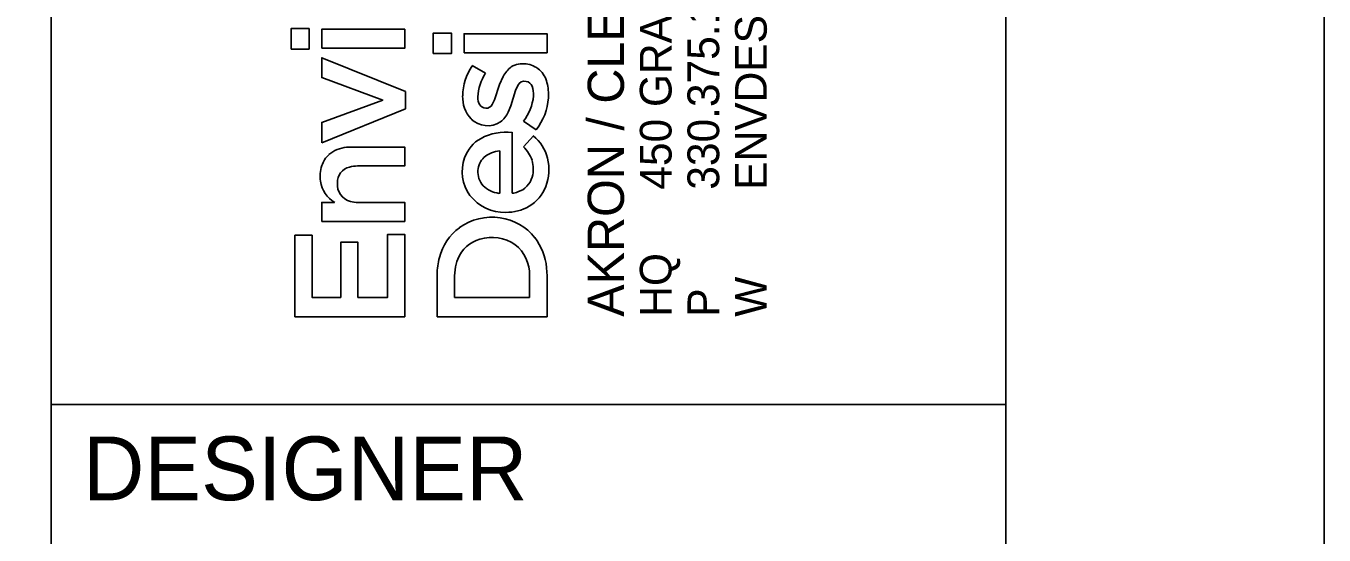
# Model space of a CAD drawing. Extents: x -0.2 to 34, y 0 to 22.
# Drawn here: x 31.961 to 34, y 2.295 to 3.094 of the extents above; entities that cross this region are included whole.
import ezdxf

# ---------------------------------------------------------------- set-up
doc = ezdxf.new("R2010")
doc.units = 0
for name, color, linetype in [('SH_Border', 7, 'Continuous'), ('SH_Cut_Line', 7, 'Continuous'), ('SH_Data', 7, 'Continuous')]:
    doc.layers.add(name, color=color, linetype=linetype)

msp = doc.modelspace()

# ---------------------------------------------------------------- linework, layer by layer
at = {"layer": 'SH_Border'}
for p, q in [((32, 0.5), (32, 21.5)), ((32, 2.5), (33.5, 2.5))]:
    msp.add_line(p, q, dxfattribs=at)
msp.add_lwpolyline([(1.5, 21.5), (33.5, 21.5), (33.5, 0.5), (1.5, 0.5)], close=True, dxfattribs=at)
at = {"layer": 'SH_Cut_Line'}
msp.add_lwpolyline([(0, 0), (34, 0), (34, 22), (0, 22)], close=True, dxfattribs=at)
at = {"layer": 'SH_Data'}
for p, q in [((32.3771, 3.0582), (32.3771, 3.0903)), ((32.3771, 3.0903), (32.4054, 3.0903)), ((32.4054, 3.0903), (32.4054, 3.0582)), ((32.4254, 3.0594), (32.4254, 3.0893)), ((32.4254, 3.0893), (32.5557, 3.0893)), ((32.5557, 3.0893), (32.5557, 3.0594)), ((32.6005, 3.0511), (32.6005, 3.0832)), ((32.6005, 3.0832), (32.6289, 3.0832)), ((32.6289, 3.0832), (32.6289, 3.0511)), ((32.6489, 3.0523), (32.6489, 3.0822)), ((32.6489, 3.0822), (32.7792, 3.0822)), ((32.7792, 3.0822), (32.7792, 3.0523)), ((32.5557, 3.0594), (32.4254, 3.0594)), ((32.4054, 3.0582), (32.3771, 3.0582)), ((32.4254, 3.0133), (32.4254, 3.0446)), ((32.4254, 3.0446), (32.5567, 2.9913)), ((32.6289, 3.0511), (32.6005, 3.0511)), ((32.7792, 3.0523), (32.6489, 3.0523)), ((32.6615, 3.0321), (32.6827, 3.0203)), ((32.5212, 2.978), (32.4254, 3.0133)), ((32.6967, 2.9787), (32.7048, 3.0026)), ((32.7048, 3.0026), (32.7104, 3.0153)), ((32.7334, 3.001), (32.7298, 2.9933)), ((32.4254, 2.9429), (32.5212, 2.978)), ((32.5567, 2.9913), (32.5567, 2.9644)), ((32.693, 2.9712), (32.6967, 2.9787)), ((32.7298, 2.9933), (32.7221, 2.9688)), ((32.5567, 2.9644), (32.4254, 2.9109)), ((32.7221, 2.9688), (32.7182, 2.9592)), ((32.4254, 2.9109), (32.4254, 2.9429)), ((32.7621, 2.9314), (32.742, 2.9447)), ((32.7245, 2.9275), (32.7246, 2.8319)), ((32.7423, 2.9046), (32.7577, 2.922)), ((32.4644, 2.904), (32.4729, 2.9044)), ((32.4729, 2.9044), (32.5557, 2.9044)), ((32.5557, 2.9044), (32.5557, 2.8746)), ((32.7049, 2.8318), (32.7049, 2.8983)), ((32.5557, 2.8746), (32.4814, 2.8746)), ((32.4254, 2.7875), (32.4254, 2.8173)), ((32.4254, 2.8173), (32.4455, 2.8173)), ((32.4822, 2.8173), (32.5557, 2.8173)), ((32.5557, 2.8173), (32.5557, 2.7876)), ((32.7036, 2.8317), (32.7049, 2.8318)), ((32.5557, 2.7876), (32.4254, 2.7875)), ((32.383, 2.6379), (32.383, 2.766)), ((32.383, 2.766), (32.4101, 2.766)), ((32.4101, 2.766), (32.4101, 2.6683)), ((32.455, 2.6683), (32.455, 2.7549)), ((32.455, 2.7549), (32.4822, 2.7549)), ((32.4822, 2.7549), (32.4822, 2.6683)), ((32.5286, 2.6683), (32.5286, 2.7672)), ((32.5286, 2.7672), (32.5557, 2.7672)), ((32.5557, 2.7672), (32.5557, 2.6379)), ((32.7785, 2.715), (32.7792, 2.7021)), ((32.6064, 2.638), (32.6064, 2.704)), ((32.6347, 2.7118), (32.6341, 2.7023)), ((32.6341, 2.7023), (32.6341, 2.6684)), ((32.7515, 2.6683), (32.7515, 2.7024)), ((32.7792, 2.7021), (32.7792, 2.638)), ((32.4101, 2.6683), (32.455, 2.6683)), ((32.4822, 2.6683), (32.5286, 2.6683)), ((32.6341, 2.6684), (32.7515, 2.6683)), ((32.5557, 2.6379), (32.383, 2.6379)), ((32.7792, 2.638), (32.6064, 2.638))]:
    msp.add_line(p, q, dxfattribs=at)
for points in [[(32.3771, 3.0582), (32.3771, 3.0903), (32.4054, 3.0903), (32.4054, 3.0582)], [(32.4254, 3.0594), (32.4254, 3.0893), (32.5557, 3.0893), (32.5557, 3.0594)], [(32.6005, 3.0511), (32.6005, 3.0832), (32.6289, 3.0832), (32.6289, 3.0511)], [(32.6489, 3.0523), (32.6489, 3.0822), (32.7792, 3.0822), (32.7792, 3.0523)], [(32.4254, 2.9109), (32.4254, 2.9429), (32.5212, 2.978), (32.4254, 3.0133), (32.4254, 3.0446), (32.5567, 2.9913), (32.5567, 2.9644)], [(32.383, 2.6379), (32.383, 2.766), (32.4101, 2.766), (32.4101, 2.6683), (32.455, 2.6683), (32.455, 2.7549), (32.4822, 2.7549), (32.4822, 2.6683), (32.5286, 2.6683), (32.5286, 2.7672), (32.5557, 2.7672), (32.5557, 2.6379)]]:
    msp.add_lwpolyline(points, close=True, dxfattribs=at)
for points in [[(32.6615, 3.0321), (32.6827, 3.0203)], [(32.693, 2.9712), (32.6967, 2.9787), (32.7048, 3.0026), (32.7104, 3.0153)], [(32.7334, 3.001), (32.7298, 2.9933), (32.7221, 2.9688), (32.7182, 2.9592)], [(32.7621, 2.9314), (32.742, 2.9447)], [(32.7245, 2.9275), (32.7246, 2.8319)], [(32.7423, 2.9046), (32.7577, 2.922)], [(32.4644, 2.904), (32.4729, 2.9044), (32.5557, 2.9044), (32.5557, 2.8746), (32.4814, 2.8746)], [(32.7036, 2.8317), (32.7049, 2.8318), (32.7049, 2.8983)], [(32.4254, 2.7875), (32.4254, 2.8173), (32.4455, 2.8173)], [(32.4822, 2.8173), (32.5557, 2.8173), (32.5557, 2.7876), (32.4254, 2.7875)], [(32.7785, 2.715), (32.7792, 2.7021), (32.7792, 2.638), (32.6064, 2.638)], [(32.6064, 2.638), (32.6064, 2.704)], [(32.6347, 2.7118), (32.6341, 2.7023), (32.6341, 2.6684), (32.7515, 2.6683), (32.7515, 2.7024)]]:
    msp.add_lwpolyline(points, dxfattribs=at)
for centre, radius, start, end in [((32.7364, 2.9826), 0.0897, 146.531, 178.7571), ((32.7364, 2.9826), 0.0897, 146.531, 178.7571), ((32.7452, 2.9789), 0.0749, 146.5112, 176.9101), ((32.7452, 2.9789), 0.0749, 146.5112, 176.9101), ((32.7466, 2.9971), 0.0405, 125.5118, 153.4159), ((32.7466, 2.9971), 0.0405, 125.5118, 153.4159), ((32.7406, 3.0026), 0.0326, 80.1719, 122.5197), ((32.7406, 3.0026), 0.0326, 80.1719, 122.5197), ((32.7428, 2.9982), 0.0367, 47.7934, 84.6892), ((32.7428, 2.9982), 0.0367, 47.7934, 84.6892), ((32.7379, 2.9946), 0.0427, 14.9966, 46.2063), ((32.7379, 2.9946), 0.0427, 14.9966, 46.2063), ((32.7438, 2.9963), 0.0114, 76.6609, 155.7053), ((32.7438, 2.9963), 0.0114, 76.6609, 155.7053), ((32.744, 2.9951), 0.0126, 21.5098, 78.5262), ((32.744, 2.9951), 0.0126, 21.5098, 78.5262), ((32.7259, 2.9877), 0.0321, 354.5726, 22.068), ((32.7259, 2.9877), 0.0321, 354.5726, 22.068), ((32.7104, 2.9867), 0.0712, 355.8306, 15.3914), ((32.7104, 2.9867), 0.0712, 355.8306, 15.3914), ((32.6967, 2.9824), 0.0501, 177.5366, 222.7932), ((32.6967, 2.9824), 0.0501, 177.5366, 222.7932), ((32.6931, 2.9823), 0.0228, 178.4747, 211.0868), ((32.6931, 2.9823), 0.0228, 178.4747, 211.0868), ((32.6825, 2.9915), 0.0757, 321.811, 354.7969), ((32.6825, 2.9915), 0.0757, 321.811, 354.7969), ((32.6895, 2.9882), 0.0922, 321.9777, 355.8738), ((32.6895, 2.9882), 0.0922, 321.9777, 355.8738), ((32.6833, 2.9767), 0.0115, 212.2368, 268.3777), ((32.6833, 2.9767), 0.0115, 212.2368, 268.3777), ((32.6834, 2.9759), 0.0107, 267.716, 333.7337), ((32.6834, 2.9759), 0.0107, 267.716, 333.7337), ((32.681, 2.9758), 0.0408, 308.0877, 335.9874), ((32.681, 2.9758), 0.0408, 308.0877, 335.9874), ((32.686, 2.9753), 0.0375, 225.9854, 302.4797), ((32.686, 2.9753), 0.0375, 225.9854, 302.4797), ((32.7024, 2.8691), 0.0558, 118.8308, 160.6244), ((32.7024, 2.8691), 0.0558, 118.8308, 160.6244), ((32.7152, 2.8441), 0.0838, 83.615, 118.2876), ((32.7152, 2.8441), 0.0838, 83.615, 118.2876), ((32.7174, 2.8717), 0.0644, 13.5336, 51.3615), ((32.7174, 2.8717), 0.0644, 13.5336, 51.3615), ((32.4687, 2.8543), 0.0499, 94.9696, 130.2225), ((32.4687, 2.8543), 0.0499, 94.9696, 130.2225), ((32.7079, 2.8561), 0.0424, 94.008, 130.8817), ((32.7079, 2.8561), 0.0424, 94.008, 130.8817), ((32.7038, 2.8656), 0.0549, 19.0357, 45.4406), ((32.7038, 2.8656), 0.0549, 19.0357, 45.4406), ((32.4635, 2.8626), 0.0402, 132.2219, 161.6818), ((32.4635, 2.8626), 0.0402, 132.2219, 161.6818), ((32.7104, 2.8661), 0.0644, 160.5201, 215.7831), ((32.7104, 2.8661), 0.0644, 160.5201, 215.7831), ((32.7005, 2.8663), 0.0298, 132.9851, 177.179), ((32.7005, 2.8663), 0.0298, 132.9851, 177.179), ((32.7107, 2.8697), 0.047, 344.6059, 17.007), ((32.7107, 2.8697), 0.047, 344.6059, 17.007), ((32.7064, 2.8692), 0.0758, 339.3542, 13.3785), ((32.7064, 2.8692), 0.0758, 339.3542, 13.3785), ((32.4787, 2.8582), 0.056, 162.2736, 187.7919), ((32.4787, 2.8582), 0.056, 162.2736, 187.7919), ((32.4748, 2.8487), 0.025, 103.6865, 182.2187), ((32.4748, 2.8487), 0.025, 103.6865, 182.2187), ((32.4811, 2.8286), 0.046, 89.6049, 105.3284), ((32.4811, 2.8286), 0.046, 89.6049, 105.3284), ((32.7017, 2.865), 0.0311, 175.0013, 223.283), ((32.7017, 2.865), 0.0311, 175.0013, 223.283), ((32.7224, 2.8671), 0.035, 288.0077, 343.5508), ((32.7224, 2.8671), 0.035, 288.0077, 343.5508), ((32.4703, 2.858), 0.0476, 188.962, 238.7037), ((32.4703, 2.858), 0.0476, 188.962, 238.7037), ((32.4773, 2.8456), 0.0276, 175.5854, 255.1439), ((32.4773, 2.8456), 0.0276, 175.5854, 255.1439), ((32.7089, 2.8736), 0.0423, 225.0619, 262.7974), ((32.7089, 2.8736), 0.0423, 225.0619, 262.7974), ((32.7189, 2.8652), 0.0626, 300.9427, 338.7323), ((32.7189, 2.8652), 0.0626, 300.9427, 338.7323), ((32.4818, 2.8595), 0.0422, 254.0916, 270.5284), ((32.4818, 2.8595), 0.0422, 254.0916, 270.5284), ((32.7125, 2.8705), 0.0687, 217.7452, 271.6543), ((32.7125, 2.8705), 0.0687, 217.7452, 271.6543), ((32.7247, 2.8522), 0.0202, 269.7003, 294.8711), ((32.7247, 2.8522), 0.0202, 269.7003, 294.8711), ((32.6923, 2.7079), 0.0864, 81.194, 125.9984), ((32.6923, 2.7079), 0.0864, 81.194, 125.9984), ((32.7155, 2.8724), 0.0706, 269.2048, 300.3341), ((32.7155, 2.8724), 0.0706, 269.2048, 300.3341), ((32.6939, 2.7089), 0.0865, 127.2362, 165.148), ((32.6939, 2.7089), 0.0865, 127.2362, 165.148), ((32.6946, 2.7113), 0.0827, 37.8521, 82.402), ((32.6946, 2.7113), 0.0827, 37.8521, 82.402), ((32.6889, 2.7078), 0.054, 106.1881, 157.3861), ((32.6889, 2.7078), 0.054, 106.1881, 157.3861), ((32.6928, 2.6986), 0.0639, 55.6727, 107.2093), ((32.6928, 2.6986), 0.0639, 55.6727, 107.2093), ((32.6859, 2.7057), 0.0931, 5.7333, 37.304), ((32.6859, 2.7057), 0.0931, 5.7333, 37.304), ((32.6929, 2.705), 0.0587, 357.4662, 52.2665), ((32.6929, 2.705), 0.0587, 357.4662, 52.2665), ((32.7143, 2.7028), 0.1078, 164.7861, 179.3704), ((32.7143, 2.7028), 0.1078, 164.7861, 179.3704), ((32.6983, 2.7039), 0.0641, 157.3571, 172.9275), ((32.6983, 2.7039), 0.0641, 157.3571, 172.9275)]:
    msp.add_arc(centre, radius, start, end, dxfattribs=at)

# ---------------------------------------------------------------- texts
for s, height, p in [('450 GRANT ST., AKRON, OH  44311', 0.049846, (32.9749, 2.8374)), ('AKRON / CLEVELAND / COLUMBUS', 0.056969, (32.9001, 2.638)), ('ENVDESIGNGROUP.COM', 0.049846, (33.1244, 2.8374)), ('330.375.1390', 0.049846, (33.0497, 2.8374)), ('HQ ', 0.04985, (32.9749, 2.638)), ('W', 0.0498, (33.1244, 2.638)), ('P', 0.0498, (33.0497, 2.638))]:
    msp.add_text(s, height=height, rotation=90, dxfattribs=at).set_placement(p)
msp.add_text('DESIGNER', height=0.1, dxfattribs=at).set_placement((32.05, 2.35))

doc.saveas('drawing.dxf')
